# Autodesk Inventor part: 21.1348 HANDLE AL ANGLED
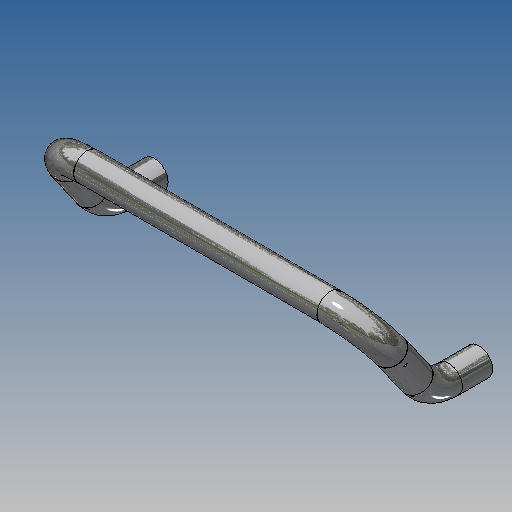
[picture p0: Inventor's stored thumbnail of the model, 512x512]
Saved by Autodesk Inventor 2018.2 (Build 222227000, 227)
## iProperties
Created: 2007-02
Part Number: 21.1348 HANDLE AL ANGLED
Document SubType Name: Modeling
Designer: Andy Moles
Material: Aluminum-6061
Mass: 45.285 g
Surface Area: 72.9484 cm^2
Volume: 16.7722 cm^3
Density: 2.7 g/cm^3
Appearance: Aluminum - Flat
Author: Andy Moles
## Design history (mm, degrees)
feature "Base1"
thread "Thread1" dims "d0" = 10, "d1" = 0
thread "Thread2" dims "d2" = 10, "d3" = 0
workplane "Work Plane1"
sketch "Sketch1"
  geometry: C1 r 2.5 at (0, 0) reference; C2 r 2.5 at (120, 0) reference; 1 further point
extrude "Extrusion1" join sketch "Sketch1" distance "d5" = 3; taper "d6" = 0 deg
body "Solid1"
other parameters: "d4" = -13
